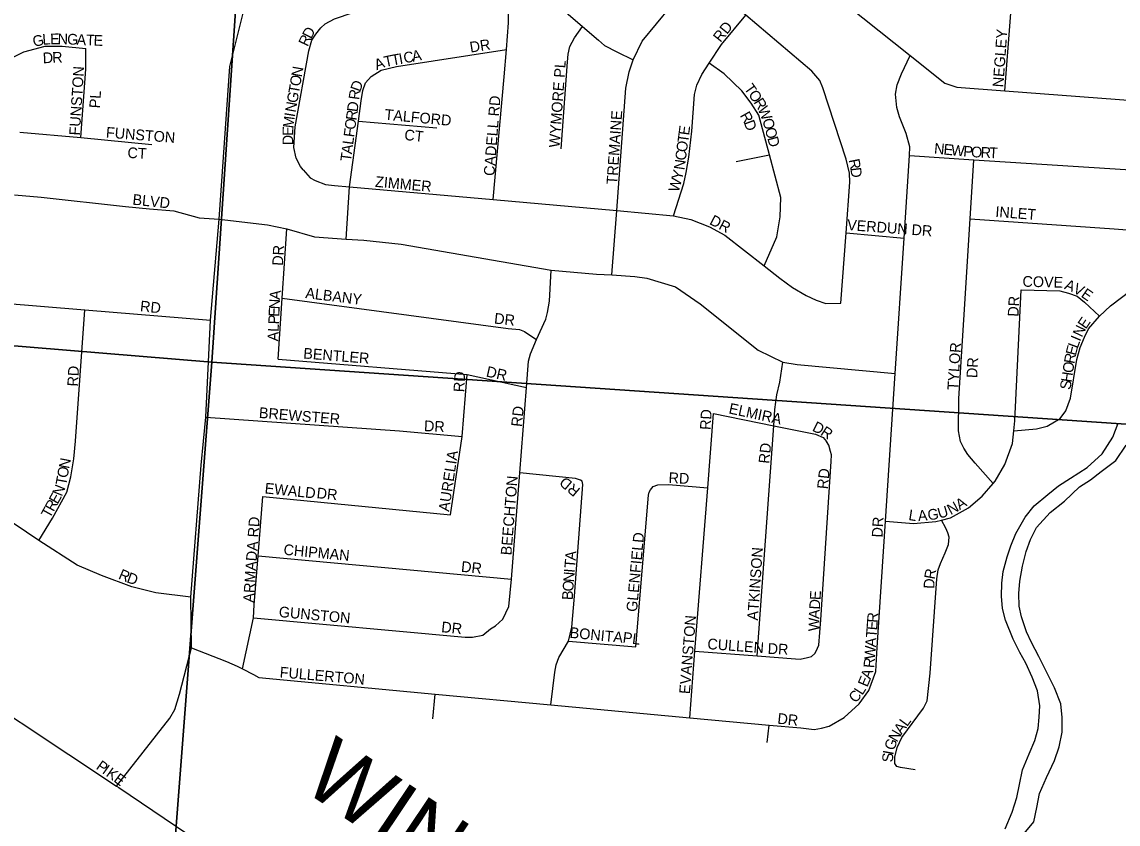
# Model space of a CAD drawing. Extents: x 0 to 34, y 0 to 22.
# Drawn here: x 7.024 to 7.992, y 16.637 to 17.345 of the extents above; entities that cross this region are included whole.
import ezdxf

# ---------------------------------------------------------------- set-up
doc = ezdxf.new("R2010")
doc.units = 0
for name, color, linetype in [('GM_X_City_Street', 7, 'Continuous'), ('GM_X_City_Street_Text', 7, 'Continuous'), ('GM_X_County_Road', 7, 'Continuous'), ('GM_X_County_Road_Text', 7, 'Continuous'), ('GM_X_Minor_River', 7, 'Continuous'), ('GM_X_Section', 7, 'Continuous'), ('GM_X_Township_Subdivision', 7, 'Continuous'), ('GM_X_Township_Subdivision_Text', 7, 'Continuous')]:
    doc.layers.add(name, color=color, linetype=linetype)

msp = doc.modelspace()

# ---------------------------------------------------------------- linework, layer by layer
at = {"layer": 'GM_X_City_Street'}
msp.add_lwpolyline([(6.59043, 16.98228), (6.59653, 16.97983), (6.66547, 16.95449), (6.70247, 16.93573), (6.7917, 16.87997), (6.9382, 16.78263), (7.10773, 16.6702), (7.10975, 16.66884)], dxfattribs=at)
at = {"layer": 'GM_X_County_Road'}
for points in [[(7.10773, 16.6702), (7.15483, 16.7302), (7.15919, 16.73768), (7.16334, 16.75125), (7.17393, 16.79226), (7.17343, 16.83687), (7.18255, 16.95347), (7.18661, 16.99606), (7.19067, 17.08173), (7.19827, 17.17095), (7.20767, 17.30576), (7.22006, 17.35497)], [(7.10975, 16.66884), (7.25082, 16.57357), (7.32264, 16.52581), (7.36269, 16.4984), (7.41818, 16.46116), (7.47523, 16.42339), (7.62451, 16.32351), (7.65946, 16.29869), (7.67897, 16.28418), (7.68753, 16.27741)]]:
    msp.add_lwpolyline(points, dxfattribs=at)
at = {"layer": 'GM_X_Minor_River'}
for points in [[(7.89194, 16.63232), (7.89808, 16.64708), (7.90232, 16.65995), (7.90466, 16.6717), (7.90739, 16.68459), (7.91315, 16.69859), (7.91814, 16.71033), (7.92123, 16.72093), (7.92205, 16.73117), (7.92248, 16.74104), (7.92068, 16.75433), (7.91584, 16.7665), (7.91024, 16.77868), (7.905, 16.7882), (7.89902, 16.8), (7.89232, 16.81674), (7.88974, 16.827), (7.88867, 16.83801), (7.88912, 16.84939), (7.89032, 16.85963), (7.8938, 16.87251), (7.89688, 16.88235), (7.90149, 16.89333), (7.90952, 16.9077), (7.91752, 16.91752), (7.92969, 16.92769), (7.93918, 16.93522), (7.94981, 16.94199), (7.96424, 16.95139), (7.97755, 16.96345), (7.98709, 16.97819), (7.99171, 16.99069)], [(7.90437, 16.62313), (7.91732, 16.63861), (7.92004, 16.65112), (7.92239, 16.66363), (7.92852, 16.67763), (7.93542, 16.69277), (7.93966, 16.70488), (7.94238, 16.71777), (7.94246, 16.73067), (7.94103, 16.74282), (7.93544, 16.75689), (7.92872, 16.7706), (7.92162, 16.78468), (7.91527, 16.79686), (7.91079, 16.80638), (7.90633, 16.81969), (7.9045, 16.82918), (7.90419, 16.84019), (7.90501, 16.85119), (7.90736, 16.86446), (7.91047, 16.87734), (7.91431, 16.88794), (7.91967, 16.89853), (7.93186, 16.91174), (7.9444, 16.92191), (7.95771, 16.93435), (7.9672, 16.94074), (7.9767, 16.9479), (7.98962, 16.95769), (7.99877, 16.97129)]]:
    msp.add_lwpolyline(points, dxfattribs=at)
at = {"layer": 'GM_X_Section'}
for points in [[(6.20871, 18.0808), (6.24469, 18.0791), (6.75111, 18.03752), (7.25608, 17.99704), (7.19182, 17.04453), (6.14388, 17.13103)], [(7.25608, 17.99704), (7.7594, 17.95531), (8.26119, 17.91328), (8.28732, 17.91243), (8.21553, 16.97509), (7.19182, 17.04453)], [(6.14388, 17.13103), (7.19182, 17.04453), (7.11329, 16.02199), (6.07795, 16.10891)], [(7.19182, 17.04453), (8.21553, 16.97509), (8.13661, 15.94799), (7.11329, 16.02199)]]:
    msp.add_lwpolyline(points, close=True, dxfattribs=at)
at = {"layer": 'GM_X_Township_Subdivision'}
for points in [[(7.57076, 17.5057), (7.65892, 17.43461), (7.7118, 17.39237), (7.80817, 17.3154), (7.83868, 17.29103), (7.84924, 17.28744), (7.89162, 17.28422), (8.17216, 17.26292), (8.1911, 17.26186), (8.20059, 17.26323), (8.21734, 17.26789), (8.22687, 17.27078), (8.23682, 17.27708), (8.2491, 17.28638), (8.25601, 17.29159), (8.26518, 17.29638), (8.2759, 17.30304), (8.29359, 17.31871)], [(7.89162, 17.28422), (7.89665, 17.34891), (7.90108, 17.40585), (7.90503, 17.4567), (7.90513, 17.46277), (7.90631, 17.46541), (7.90747, 17.46691), (7.91657, 17.46715)], [(7.54485, 17.12154), (7.54917, 17.17842), (7.55737, 17.2864), (7.56025, 17.30079), (7.56361, 17.31139), (7.57168, 17.32795), (7.59686, 17.35873), (7.62042, 17.38754), (7.65892, 17.43461)], [(7.74685, 17.09652), (7.7516, 17.15869), (7.75502, 17.20349), (7.75477, 17.21147), (7.75156, 17.22368), (7.73097, 17.28667), (7.72842, 17.29316), (7.72135, 17.30163), (7.66326, 17.35108), (7.62042, 17.38754)], [(7.28797, 17.33969), (7.29183, 17.34343), (7.30023, 17.34785), (7.31662, 17.35329), (7.45026, 17.37423), (7.46327, 17.37487), (7.47159, 17.37322), (7.48363, 17.36771), (7.50425, 17.35371), (7.51912, 17.34092), (7.53304, 17.32894), (7.53827, 17.32431), (7.54917, 17.31843), (7.56361, 17.31139)], [(7.44018, 17.18808), (7.44988, 17.29647), (7.45181, 17.32072), (7.45369, 17.34427), (7.45381, 17.35224), (7.45316, 17.35908), (7.45026, 17.37423)], [(7.59917, 17.17384), (7.60832, 17.20241), (7.61036, 17.21188), (7.61286, 17.22551), (7.61551, 17.24863), (7.61792, 17.28087), (7.61995, 17.2892), (7.62427, 17.29863), (7.63083, 17.3087), (7.64176, 17.32493), (7.66326, 17.35108)], [(7.27231, 17.21423), (7.27008, 17.2173), (7.26641, 17.22458), (7.26429, 17.2341), (7.26534, 17.25232), (7.27742, 17.31935), (7.28022, 17.3288), (7.28371, 17.33406), (7.28797, 17.33969)], [(7.50003, 17.233), (7.50581, 17.30963), (7.5063, 17.31646), (7.50793, 17.32327), (7.51184, 17.3308), (7.51912, 17.34092)], [(6.81112, 17.27161), (6.82064, 17.26894), (6.85303, 17.2617), (6.86941, 17.26018), (6.88504, 17.25789), (6.92809, 17.25484), (6.93769, 17.25459), (6.94523, 17.25108), (6.94861, 17.24875), (6.95201, 17.2472), (6.95544, 17.24867), (6.95589, 17.25474), (6.95635, 17.26043), (6.97039, 17.27237), (6.97458, 17.28456), (6.97797, 17.29053), (6.98677, 17.29828), (7.00773, 17.30933), (7.0259, 17.31847), (7.04466, 17.32354), (7.05987, 17.32354), (7.08066, 17.32152)], [(7.07609, 17.24294), (7.08066, 17.30326), (7.08066, 17.32152)], [(7.33239, 17.29682), (7.34119, 17.30238), (7.35489, 17.30558), (7.45181, 17.32072)], [(7.67924, 17.12948), (7.69056, 17.15514), (7.6935, 17.17295), (7.69416, 17.19003), (7.68392, 17.22773), (7.67448, 17.26251), (7.66783, 17.27324), (7.65966, 17.28401), (7.64399, 17.29907), (7.63083, 17.3087)], [(7.75005, 16.73073), (7.76313, 16.74267), (7.77167, 16.75469), (7.778, 16.7713), (7.7791, 16.79255), (7.78644, 16.90402), (7.79503, 17.03459), (7.8029, 17.15413), (7.80769, 17.22692), (7.80783, 17.23455), (7.80461, 17.24637), (7.79878, 17.26128), (7.79626, 17.2693), (7.79532, 17.28108), (7.79658, 17.28942), (7.80053, 17.29923), (7.80817, 17.3154)], [(7.31031, 17.15321), (7.31337, 17.19932), (7.32126, 17.25735), (7.3237, 17.27531), (7.32498, 17.28441), (7.32737, 17.29121), (7.33239, 17.29682)], [(7.32126, 17.25735), (7.39041, 17.25146)], [(7.02236, 17.2475), (7.07609, 17.24294), (7.13896, 17.23686)], [(7.80769, 17.22692), (7.86449, 17.22324), (8.07201, 17.20981), (8.0951, 17.2087), (8.10611, 17.21004), (8.113, 17.21373), (8.11816, 17.22215), (8.12323, 17.2375)], [(7.65449, 17.22181), (7.68392, 17.22773)], [(7.88134, 16.9374), (7.86549, 16.95524), (7.85917, 16.96294), (7.85547, 16.9687), (7.85253, 16.97444), (7.85079, 16.98396), (7.85125, 17.01244), (7.8554, 17.08187), (7.86114, 17.17099), (7.86449, 17.22324)], [(7.27231, 17.21423), (7.27864, 17.20729), (7.28315, 17.20494), (7.29219, 17.20137), (7.30013, 17.20049), (7.31337, 17.19932), (7.44018, 17.18808), (7.54917, 17.17842), (7.59917, 17.17384), (7.61463, 17.17041), (7.6312, 17.16407), (7.64473, 17.15664), (7.67924, 17.12948), (7.69301, 17.11865), (7.70425, 17.11049), (7.71626, 17.10347), (7.72529, 17.09914), (7.73359, 17.09635), (7.74685, 17.09652)], [(7.89962, 16.98395), (7.9198, 16.98552), (7.92894, 16.98803), (7.94042, 16.99468), (7.94545, 17.00144), (7.94981, 17.01276), (7.95528, 17.04686), (7.9581, 17.05745), (7.96204, 17.0665), (7.96558, 17.07404), (7.97525, 17.08527), (7.98485, 17.09424), (8.01171, 17.1147), (8.03129, 17.13034), (8.04395, 17.14086), (8.04475, 17.14152), (8.05592, 17.15311), (8.05969, 17.15958), (8.06294, 17.16516), (8.06811, 17.18027), (8.07201, 17.20981)], [(7.0178, 17.19224), (7.04112, 17.19022), (7.11564, 17.18211), (7.13693, 17.18007), (7.15822, 17.17805), (7.18053, 17.17197), (7.19827, 17.17095), (7.24085, 17.16588), (7.25809, 17.16233), (7.28242, 17.15524), (7.31031, 17.15321), (7.32602, 17.15219), (7.35897, 17.14865), (7.49146, 17.12577), (7.53122, 17.12237), (7.54485, 17.12154), (7.5653, 17.1203), (7.57588, 17.11861), (7.60116, 17.111), (7.62296, 17.0961), (7.67402, 17.05522), (7.69587, 17.04445), (7.70846, 17.04244), (7.79503, 17.03459)], [(7.25049, 17.04726), (7.25403, 17.10099), (7.25809, 17.16233)], [(7.86114, 17.17099), (7.98822, 17.16217), (8.0151, 17.16022), (8.02115, 17.15898), (8.02829, 17.15508), (8.04395, 17.14086)], [(7.7516, 17.15869), (7.8029, 17.15413)], [(7.44207, 16.8116), (7.44861, 16.81757), (7.4541, 16.82888), (7.4564, 16.85277), (7.46378, 16.94682), (7.46969, 17.02225), (7.47123, 17.04547), (7.47323, 17.05189), (7.4785, 17.06451), (7.48661, 17.08244), (7.48823, 17.08849), (7.4899, 17.09834), (7.49146, 17.12577)], [(6.7846, 17.04675), (6.79899, 17.08472), (6.80488, 17.10049), (6.81451, 17.11113), (6.82871, 17.11215), (6.9301, 17.10302), (7.07964, 17.09085), (7.19067, 17.08173)], [(7.78644, 16.90402), (7.81119, 16.90218), (7.83093, 16.90376), (7.83583, 16.90498), (7.84386, 16.90698), (7.85955, 16.91584), (7.87185, 16.92628), (7.88134, 16.9374), (7.88305, 16.93939), (7.89162, 16.95406), (7.89836, 16.97257), (7.89962, 16.98395), (7.90059, 16.99266), (7.90624, 17.10841)], [(7.90624, 17.10841), (7.94034, 17.10749), (7.94789, 17.10546), (7.95542, 17.10269), (7.96217, 17.09764), (7.97525, 17.08527)], [(7.25403, 17.10099), (7.45351, 17.07423), (7.46334, 17.07332), (7.46787, 17.07173), (7.47161, 17.069), (7.4785, 17.06451)], [(7.03909, 16.88706), (7.05126, 16.90683), (7.06393, 16.92964), (7.06747, 16.94333), (7.07001, 16.95905), (7.07153, 16.97476), (7.07964, 17.09085)], [(7.17343, 16.83687), (7.1425, 16.84093), (7.12121, 16.846), (7.09434, 16.85614), (7.07305, 16.86526), (7.03909, 16.88706), (7.01729, 16.90176), (6.90779, 16.97476), (6.85405, 17.01177), (6.82871, 17.02647), (6.81096, 17.0361), (6.79626, 17.04168), (6.7846, 17.04675), (6.75266, 17.0574), (6.72478, 17.06348), (6.70349, 17.06652), (6.67358, 17.06855)], [(7.25049, 17.04726), (7.41727, 17.03357), (7.46969, 17.02225)], [(7.67322, 16.78526), (7.68783, 16.98844), (7.68887, 17.00287), (7.6906, 17.01576), (7.69304, 17.02674), (7.69587, 17.04445)], [(7.40234, 16.90984), (7.41271, 16.97882), (7.41727, 17.03357)], [(7.61357, 16.73059), (7.61818, 16.78946), (7.62947, 16.93351), (7.63461, 16.99918)], [(7.63461, 16.99918), (7.68783, 16.98844), (7.72453, 16.98104), (7.7313, 16.97789), (7.73428, 16.97443)], [(7.18661, 16.99606), (7.35745, 16.98389), (7.41271, 16.97882)], [(7.72406, 16.78735), (7.72522, 16.78923), (7.72759, 16.79451), (7.72946, 16.81689), (7.73854, 16.95689), (7.73863, 16.96258), (7.73793, 16.96563), (7.7365, 16.97135), (7.73428, 16.97443)], [(7.491, 16.74198), (7.49448, 16.77089), (7.49572, 16.77732), (7.4981, 16.78374), (7.50672, 16.79822), (7.50952, 16.81053), (7.51185, 16.83783), (7.51913, 16.93646), (7.5188, 16.9395), (7.5173, 16.94029), (7.51277, 16.94188), (7.46378, 16.94682)], [(7.5661, 16.79329), (7.57735, 16.92718), (7.57777, 16.92983), (7.57894, 16.93171), (7.58127, 16.93471), (7.58545, 16.93616), (7.59494, 16.93639), (7.62947, 16.93351)], [(7.21892, 16.77365), (7.22872, 16.81882), (7.22935, 16.83019), (7.23279, 16.8734), (7.23696, 16.92577)], [(7.23696, 16.92577), (7.40234, 16.90984)], [(7.81261, 16.68454), (7.79976, 16.68664), (7.79636, 16.68745), (7.79451, 16.69014), (7.7946, 16.69584), (7.79663, 16.70416), (7.80095, 16.71321), (7.81993, 16.73911), (7.82307, 16.74551), (7.82574, 16.76978), (7.83163, 16.85324), (7.8329, 16.86119), (7.83488, 16.86686), (7.8392, 16.87629), (7.84197, 16.88346), (7.84245, 16.88991), (7.84138, 16.89372), (7.83955, 16.89793), (7.83583, 16.90498)], [(7.23279, 16.8734), (7.4564, 16.85277)], [(7.22872, 16.81882), (7.41538, 16.80177), (7.42182, 16.80167), (7.43094, 16.80342), (7.43786, 16.80901), (7.44207, 16.8116)], [(7.50672, 16.79822), (7.5661, 16.79329)], [(7.17393, 16.79226), (7.20467, 16.78007), (7.21407, 16.77612), (7.21892, 16.77365), (7.22874, 16.76867), (7.23324, 16.76594), (7.38904, 16.75146), (7.491, 16.74198), (7.61357, 16.73059), (7.68358, 16.72408), (7.71162, 16.72147), (7.72335, 16.72014), (7.72982, 16.72118), (7.73666, 16.72297), (7.75005, 16.73073)], [(7.61818, 16.78946), (7.67322, 16.78526), (7.70693, 16.78269), (7.71109, 16.78224), (7.71756, 16.78366), (7.72099, 16.78474), (7.72406, 16.78735)], [(7.38693, 16.72969), (7.38904, 16.75146)], [(7.68185, 16.70865), (7.68358, 16.72408)]]:
    msp.add_lwpolyline(points, dxfattribs=at)

# ---------------------------------------------------------------- texts
at = {"layer": 'GM_X_City_Street_Text'}
for s, rotation, p in [('P', 324.52902, (7.089, 16.68586)), ('I', 324.50298, (7.09443, 16.68199)), ('K', 324.49539, (7.09782, 16.67957)), ('E', 322.82956, (7.10455, 16.67477))]:
    msp.add_text(s, height=0.00947, rotation=rotation, dxfattribs=at).set_placement(p)
at = {"layer": 'GM_X_County_Road_Text'}
msp.add_text('WINCHESTER', height=0.056818, rotation=326.16319, dxfattribs=at).set_placement((7.26942, 16.66837))
at = {"layer": 'GM_X_Township_Subdivision_Text'}
for s, rotation, p in [('D', 62.92662, (7.27954, 17.32935)), ('RD', 51.33663, (7.64076, 17.32635)), ('NEGLEY', 85.91271, (7.89037, 17.28703)), ('G', 13.88252, (7.03495, 17.32277)), ('L', 4.48461, (7.04264, 17.3247)), ('E', 0.87426, (7.04913, 17.32522)), ('N', 358.84156, (7.05571, 17.32532)), ('G', 357.5076, (7.06398, 17.32515)), ('A', 357.4421, (7.0723, 17.32479)), ('T', 357.46599, (7.08063, 17.32442)), ('E', 357.46599, (7.08729, 17.32412)), ('R', 64.62956, (7.27636, 17.32264)), ('DR', 8.98031, (7.4202, 17.31783)), ('D', 2.71175, (7.04283, 17.30842)), ('R', 2.40516, (7.05114, 17.30881)), ('T', 10.63476, (7.35125, 17.30641)), ('I', 10.59817, (7.3578, 17.30764)), ('C', 10.61357, (7.36189, 17.30841)), ('A', 10.61563, (7.36926, 17.30979)), ('A', 20.21838, (7.3373, 17.30229)), ('T', 11.72259, (7.34477, 17.30506)), ('WYMORE PL', 85.86759, (7.4987, 17.2337)), ('FUNSTON', 86.42217, (7.07536, 17.24451)), ('O', 80.09202, (7.26977, 17.28765)), ('N', 80.09202, (7.2712, 17.29586)), ('T', 80.08855, (7.26862, 17.28108)), ('D', 70.47995, (7.32273, 17.28273)), ('T', 305.23598, (7.66109, 17.28628)), ('PL', 86.42621, (7.09312, 17.26851)), ('G', 80.1143, (7.26719, 17.27287)), ('R', 82.3486, (7.32186, 17.2758)), ('CADELL RD', 85.60086, (7.44121, 17.2087)), ('O', 304.93293, (7.66493, 17.28085)), ('R', 301.70934, (7.66962, 17.27413)), ('N', 80.09205, (7.26576, 17.26466)), ('D', 82.35998, (7.32042, 17.26507)), ('W', 293.09705, (7.67339, 17.26809)), ('M', 82.75074, (7.2638, 17.25075)), ('I', 80.15666, (7.26505, 17.26056)), ('O', 82.35998, (7.31831, 17.24937)), ('R', 82.35078, (7.31942, 17.25763)), ('TALFORD', 354.64365, (7.34398, 17.25868)), ('TREMAINE', 86.02657, (7.54957, 17.20119)), ('R', 299.59726, (7.65763, 17.26243)), ('O', 285.91838, (7.67754, 17.25842)), ('FUNSTON', 355.53523, (7.09812, 17.24285)), ('E', 89.18037, (7.26372, 17.24437)), ('F', 82.34673, (7.31743, 17.24277)), ('CT', 353.66247, (7.36138, 17.24082)), ('E', 82.46493, (7.61299, 17.2445)), ('D', 290.38464, (7.66116, 17.25628)), ('O', 285.14968, (7.67981, 17.25044)), ('D', 89.82511, (7.2637, 17.23606)), ('L', 82.35298, (7.31654, 17.23616)), ('O', 82.46023, (7.61102, 17.22963)), ('T', 82.49883, (7.61212, 17.2379)), ('D', 285.12287, (7.68199, 17.24239)), ('CT', 356.82219, (7.11718, 17.22491)), ('T', 82.35661, (7.31455, 17.2213)), ('A', 82.35998, (7.31543, 17.2279)), ('C', 82.47946, (7.61005, 17.22219)), ('N', 354.70266, (7.82898, 17.22868)), ('E', 354.71829, (7.83728, 17.22791)), ('W', 354.69597, (7.84392, 17.22729)), ('P', 354.71829, (7.85471, 17.22629)), ('O', 356.52485, (7.86167, 17.22565)), ('R', 357.66516, (7.87019, 17.22514)), ('T', 357.70659, (7.87769, 17.22483)), ('N', 81.68113, (7.60882, 17.2138)), ('R', 281.19562, (7.75388, 17.22314)), ('Y', 76.28414, (7.60665, 17.20475)), ('D', 277.18737, (7.75531, 17.21596)), ('ZIMMER', 354.8045, (7.33563, 17.19939)), ('W', 74.86282, (7.60376, 17.19404)), ('BLVD', 353.99459, (7.1215, 17.18367)), ('INLET', 355.71288, (7.88311, 17.17281)), ('DR', 332.1174, (7.63034, 17.16675)), ('VERDUN DR', 355.76331, (7.75228, 17.16118)), ('DR', 86.97755, (7.25457, 17.12949)), ('COVE', 358.49332, (7.90719, 17.11119)), ('A', 337.38686, (7.94361, 17.1094)), ('V', 333.31764, (7.95114, 17.10627)), ('A', 84.74618, (7.25204, 17.09932)), ('ALBANY', 352.99913, (7.27403, 17.10114)), ('E', 325.11992, (7.95828, 17.10271)), ('RD', 353.99459, (7.12817, 17.08951)), ('N', 87.2664, (7.25165, 17.09111)), ('DR', 86.98901, (7.9037, 17.0845)), ('P', 87.50479, (7.25106, 17.0778)), ('E', 87.50479, (7.25135, 17.08446)), ('DR', 353.99459, (7.44066, 17.07864)), ('E', 55.58998, (7.96313, 17.07317)), ('L', 87.50479, (7.25077, 17.07114)), ('N', 64.53947, (7.95974, 17.06598)), ('A', 87.48576, (7.2504, 17.06281)), ('I', 67.05396, (7.95816, 17.06224)), ('BENTLER', 355.38839, (7.27229, 17.04781)), ('TYLOR', 86.26602, (7.85037, 17.01952)), ('E', 76.01013, (7.95439, 17.04988)), ('L', 69.97486, (7.95592, 17.0561)), ('DR', 86.97755, (7.86729, 17.03031)), ('R', 79.79506, (7.9531, 17.04266)), ('RD', 86.98841, (7.07371, 17.02283)), ('DR', 347.46734, (7.43336, 17.03194)), ('O', 81.22392, (7.95183, 17.03449)), ('RD', 86.98901, (7.41453, 17.01783)), ('S', 81.22475, (7.94955, 17.01966)), ('H', 81.23848, (7.95057, 17.02625)), ('ELMIRA', 347.83063, (7.6475, 16.99936)), ('BREWSTER', 355.36422, (7.23312, 16.99535)), ('RD', 83.99338, (7.46538, 16.98709)), ('RD', 86.82218, (7.63204, 16.9845)), ('DR', 356.97695, (7.37891, 16.98368)), ('D', 333.73795, (7.72112, 16.98427)), ('R', 326.7746, (7.72833, 16.98074)), ('RD', 83.99458, (7.68371, 16.95459)), ('N', 79.20445, (7.06591, 16.94996)), ('AURELIA', 81.46994, (7.40122, 16.91217)), ('O', 79.22592, (7.06436, 16.94177)), ('RD', 83.9832, (7.73538, 16.93209)), ('T', 79.85117, (7.06319, 16.93524)), ('BEECHTON', 85.36421, (7.4562, 16.87371)), ('RD', 139.76064, (7.51767, 16.93221)), ('RD', 357.13923, (7.59474, 16.93785)), ('N', 67.82593, (7.05943, 16.92544)), ('EWALD', 354.1724, (7.23816, 16.92867)), ('DR', 353.99459, (7.284, 16.9245)), ('R', 61.29455, (7.05213, 16.91195)), ('E', 61.29337, (7.05573, 16.91853)), ('N', 28.07208, (7.8439, 16.90936)), ('A', 31.78779, (7.85184, 16.91362)), ('T', 61.30887, (7.04893, 16.9061)), ('L', 350.9734, (7.80626, 16.90522)), ('A', 4.81406, (7.81534, 16.90408)), ('G', 7.40636, (7.82411, 16.90483)), ('U', 16.22687, (7.83392, 16.90623)), ('ARMADA RD', 85.96291, (7.22882, 16.83198)), ('DR', 86.8215, (7.7837, 16.8895)), ('GLENFIELD', 84.73763, (7.56704, 16.82373)), ('CHIPMAN', 354.55918, (7.25482, 16.87451)), ('A', 85.3398, (7.51292, 16.8691)), ('ATKINSON', 85.97083, (7.6737, 16.8162)), ('DR', 353.99459, (7.4115, 16.85951)), ('T', 85.3418, (7.51238, 16.86246)), ('R', 336.96724, (7.10872, 16.85352)), ('D', 339.65601, (7.11606, 16.85041)), ('N', 85.3398, (7.51136, 16.85)), ('I', 85.31623, (7.51204, 16.8583)), ('D', 88.55752, (7.82953, 16.84434)), ('R', 79.64736, (7.8297, 16.85229)), ('O', 85.51411, (7.51071, 16.8417)), ('B', 87.32797, (7.51036, 16.83429)), ('D', 86.32549, (7.72844, 16.82589)), ('E', 86.28223, (7.72898, 16.83421)), ('GUNSTON', 354.80527, (7.25064, 16.81951)), ('A', 86.82865, (7.72798, 16.8176)), ('DR', 353.99459, (7.394, 16.80618)), ('EVANSTON', 85.42572, (7.6137, 16.75121)), ('W', 89.36115, (7.72786, 16.80687)), ('E', 85.67104, (7.77896, 16.80755)), ('R', 85.66371, (7.77946, 16.8142)), ('BONITA', 354.50631, (7.50732, 16.80118)), ('PL', 352.40917, (7.55405, 16.797)), ('T', 85.67104, (7.77846, 16.8009)), ('CULLEN', 355.84266, (7.62894, 16.79118)), ('DR', 356.98902, (7.68224, 16.78702)), ('A', 85.66905, (7.77783, 16.79259)), ('W', 85.6708, (7.77701, 16.78179)), ('FULLERTON', 355.06065, (7.25147, 16.76618)), ('R', 84.58859, (7.77629, 16.77413)), ('E', 67.11342, (7.7703, 16.75703)), ('A', 71.62168, (7.77318, 16.76394)), ('L', 57.32353, (7.76588, 16.74986)), ('C', 48.64274, (7.75998, 16.74298)), ('DR', 353.99459, (7.69067, 16.72534)), ('L', 53.61101, (7.80541, 16.72214)), ('N', 59.81593, (7.79652, 16.70838)), ('A', 54.4242, (7.80059, 16.71539)), ('G', 69.68445, (7.79381, 16.70096)), ('S', 86.74743, (7.79286, 16.69093)), ('I', 79.94138, (7.7932, 16.69729))]:
    msp.add_text(s, height=0.00947, rotation=rotation, dxfattribs=at).set_placement(p)

doc.saveas('drawing.dxf')
